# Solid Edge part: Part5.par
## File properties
Author: Vicky Raina
Template: Normal.par
Last saved by: MYPC
Revision: 2
Application: Solid Edge
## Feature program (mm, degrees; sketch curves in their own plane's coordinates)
body "unnamed Body 1"
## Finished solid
Body 1: solid body, 82 faces, 169 edges, 90 vertices.
  Faces by surface: cylinder 44, plane 27, torus 6, spline 3, cone 2
  Edges by curve: circle 64, ellipse 44, line 26, intersection 24, curve on surface 11
Bounding box of the edges (mm; curved faces can reach further): 3403.600 x 1854.200 x 1930.410, from (-1701.8, 0, -965.2014) to (1701.8, 1854.2, 965.2088).
Cylindrical faces by radius (mm): R63.5 x26, R76.2 x4, R95.25 x4, R317.5 x4, R342.9 x3, R558.8 x1, R965.2 x2
Conical faces (half-angle, radius in mm at the cone's reference point): 15 deg R654.5026 x1, 16.46 deg R711.4955 x1
Toroidal faces (ring radius, tube radius in mm): R408.1559 r101.6 x1, R609.6 r50.8 x1, R851.7802 r50.8 x1, R889 r76.2 x2, R983.9044 r127 x1
Planar faces by outward normal: +y 20, +z 1, -y 5, -z 1
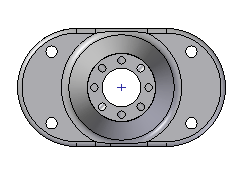
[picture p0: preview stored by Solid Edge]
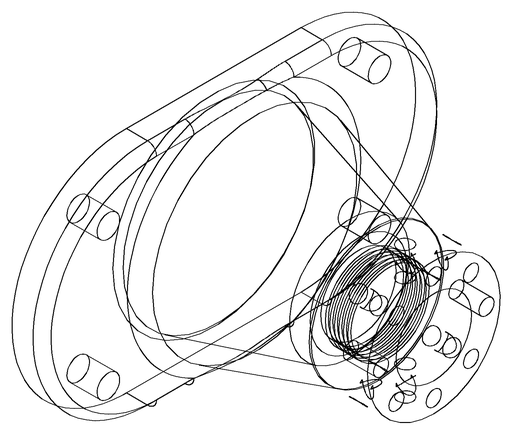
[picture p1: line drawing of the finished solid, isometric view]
